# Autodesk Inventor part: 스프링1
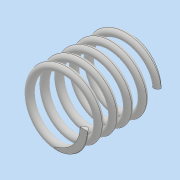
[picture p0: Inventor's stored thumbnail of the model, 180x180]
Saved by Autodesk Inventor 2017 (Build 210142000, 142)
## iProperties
Part Number: 스프링1
Material: 일반
Document SubType Name: Modeling
Designer: MRC
Density: 1 g/cm^3
Appearance: 기본값
Mass: 0.821961 g
Surface Area: 16.7185 cm^2
Volume: 0.821961 cm^3
Author: MRC
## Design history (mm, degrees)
sketch "스케치1"
  geometry: L1 (0, 0)-(0, 20.5); L2 (0, 20.5)-(20.921, 20.5); L3 (0, 0)-(8.5, 0); C1 r 1 at (8.5, 0)
  constraints: 6 end point, 2 horizontal, 1 centre point, 1 coincident, 1 vertical
  dimensions: "d0" = 20.5 distance of L1.start L1.end (derived); "d1" = 8.5 distance of L1.start L3.end; "d2" = 2 diameter of C1
feature "코일1" sketch "스케치1" pitch "d3" = 10; turns "d5" = 5; dims "d4" = 20.5 (= d0), "d6" = 0, angle "d7" = 90 deg, angle "d8" = 90 deg, "d9" = 0, "d10" = 0
sketch "스케치2"
  geometry: L1 (20.5, 11.939)-(0, 11.939); L2 (0, 11.939)-(0, -12.02); L3 (0, -12.02)-(20.5, -12.02); L4 (20.5, -12.02)-(20.5, 11.939); 1 further point
  constraints: 8 end point, 2 parallel, 1 horizontal, 1 perpendicular, 1 point on line
  dimensions: "d11" = 20.5 distance of L2.end L3.end (= d0)
extrude "돌출1" sketch "스케치2" stored distance "d12" = 0; taper "d13" = 0 deg
node "솔리드1"
